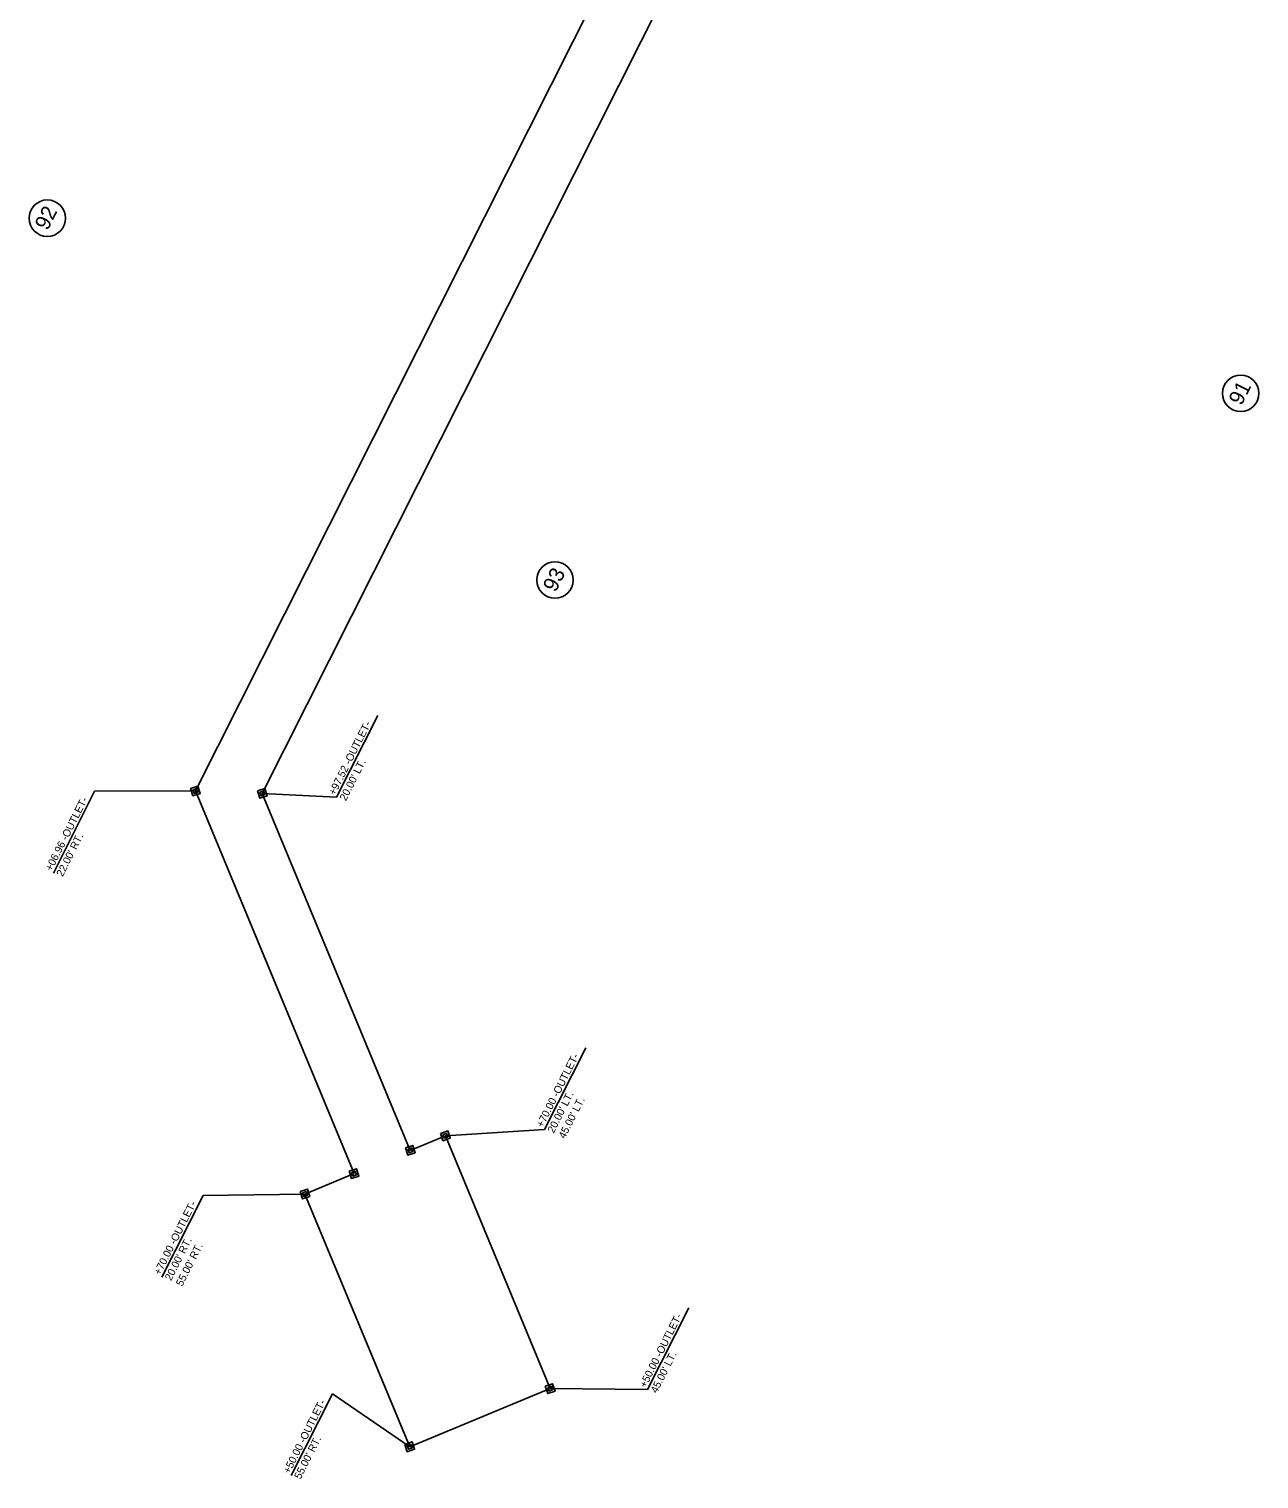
# Model space of a CAD drawing. Extents: x 2010883 to 2014849, y 442000 to 447413.
# Drawn here: x 2010883 to 2011692, y 442000 to 442954 of the extents above; entities that cross this region are included whole.
import ezdxf

# ---------------------------------------------------------------- set-up
doc = ezdxf.new("R2010")
doc.units = 0
for name, color, linetype in [('Prop Easement Permanent Drainage', 7, 'Continuous'), ('Prop Easement Permanent Drainage Station Offsets', 7, 'Continuous'), ('Prop Parcel Number CELL', 7, 'Continuous'), ('Prop Parcel Number Text', 7, 'Continuous'), ('Prop ROW Marker CELL', 7, 'Continuous'), ('Prop ROW Permanent Easement CELL', 7, 'Continuous')]:
    doc.layers.add(name, color=color, linetype=linetype)

msp = doc.modelspace()

# ---------------------------------------------------------------- linework, layer by layer
at = {"layer": 'Prop Easement Permanent Drainage'}
for p, q in [((2010992.44, 442452.82), (2011265.81, 442995.8)), ((2011036.41, 442451.2), (2011301.55, 442977.84)), ((2011096.77, 442201.11), (2010992.44, 442452.82)), ((2011133.72, 442216.42), (2011036.41, 442451.2)), ((2011156.82, 442225.99), (2011133.72, 442216.42)), ((2011225.73, 442059.71), (2011156.82, 442225.99)), ((2011064.44, 442187.71), (2011096.77, 442201.11)), ((2011133.35, 442021.42), (2011064.44, 442187.71)), ((2011133.35, 442021.42), (2011225.73, 442059.71))]:
    msp.add_line(p, q, dxfattribs=at)
at = {"layer": 'Prop Easement Permanent Drainage Station Offsets'}
for p, q in [((2011085.3, 442448.66), (2011112.38, 442502.44)), ((2010899.04, 442398.79), (2010926.12, 442452.58)), ((2010992.44, 442452.82), (2010926.12, 442452.58)), ((2011036.41, 442451.2), (2011085.3, 442448.66)), ((2011221.98, 442230.12), (2011249.06, 442283.9)), ((2011156.82, 442225.99), (2011221.98, 442230.12)), ((2010970.38, 442133.04), (2010997.46, 442186.82)), ((2011064.44, 442187.71), (2010997.46, 442186.82)), ((2011289.76, 442059.07), (2011316.84, 442112.85)), ((2011225.73, 442059.71), (2011289.76, 442059.07)), ((2011055.45, 442002.46), (2011082.53, 442056.24)), ((2011133.35, 442021.42), (2011082.53, 442056.24))]:
    msp.add_line(p, q, dxfattribs=at)
at = {"layer": 'Prop Parcel Number CELL'}
for p, q in [((2010895.01, 442829.52), (2010895.01, 442829.52)), ((2011679.82, 442714.35), (2011679.82, 442714.35)), ((2011228.88, 442591.53), (2011228.88, 442591.53))]:
    msp.add_line(p, q, dxfattribs=at)
for centre in [(2010895.01, 442829.52), (2011679.82, 442714.35), (2011228.88, 442591.53)]:
    msp.add_circle(centre, 12, dxfattribs=at)
at = {"layer": 'Prop ROW Marker CELL'}
for p, q in [((2010992.44, 442452.82), (2010992.44, 442452.82)), ((2011036.41, 442451.2), (2011036.41, 442451.2)), ((2011156.82, 442225.99), (2011156.82, 442225.99)), ((2011133.72, 442216.42), (2011133.72, 442216.42)), ((2011096.77, 442201.11), (2011096.77, 442201.11)), ((2011064.44, 442187.71), (2011064.44, 442187.71)), ((2011225.73, 442059.71), (2011225.73, 442059.71)), ((2011133.35, 442021.42), (2011133.35, 442021.42))]:
    msp.add_line(p, q, dxfattribs=at)
at = {"layer": 'Prop ROW Permanent Easement CELL'}
for points in [[(2010989.23, 442454.44), (2010994.06, 442456.04), (2010995.66, 442451.2), (2010990.82, 442449.6)], [(2010990.84, 442453.63), (2010993.25, 442454.43), (2010994.05, 442452.01), (2010991.63, 442451.21)], [(2011033.2, 442452.82), (2011038.03, 442454.42), (2011039.63, 442449.59), (2011034.79, 442447.99)], [(2011034.81, 442452.01), (2011037.22, 442452.81), (2011038.02, 442450.39), (2011035.6, 442449.6)], [(2011153.6, 442227.61), (2011158.44, 442229.21), (2011160.03, 442224.38), (2011155.2, 442222.78)], [(2011155.21, 442226.8), (2011157.63, 442227.6), (2011158.42, 442225.18), (2011156.01, 442224.39)], [(2011130.51, 442218.04), (2011135.34, 442219.64), (2011136.94, 442214.8), (2011132.1, 442213.21)], [(2011132.11, 442217.23), (2011134.53, 442218.03), (2011135.33, 442215.61), (2011132.91, 442214.81)], [(2011093.55, 442202.73), (2011098.39, 442204.32), (2011099.98, 442199.49), (2011095.15, 442197.89)], [(2011095.16, 442201.92), (2011097.58, 442202.71), (2011098.38, 442200.3), (2011095.96, 442199.5)], [(2011061.22, 442189.32), (2011066.06, 442190.92), (2011067.65, 442186.09), (2011062.82, 442184.49)], [(2011062.83, 442188.52), (2011065.25, 442189.31), (2011066.04, 442186.9), (2011063.63, 442186.1)], [(2011222.52, 442061.33), (2011227.35, 442062.93), (2011228.95, 442058.09), (2011224.12, 442056.49)], [(2011224.13, 442060.52), (2011226.54, 442061.32), (2011227.34, 442058.9), (2011224.93, 442058.1)], [(2011130.14, 442023.04), (2011134.97, 442024.64), (2011136.57, 442019.8), (2011131.74, 442018.21)], [(2011131.75, 442022.23), (2011134.16, 442023.03), (2011134.96, 442020.61), (2011132.55, 442019.81)]]:
    msp.add_lwpolyline(points, close=True, dxfattribs=at)

# ---------------------------------------------------------------- texts
at = {"layer": 'Prop Easement Permanent Drainage Station Offsets'}
for s, p in [('+97.52 -OUTLET-', (2011084.16, 442449.54)), ("20.00' LT.", (2011091.42, 442445.89)), ('+06.96 -OUTLET-', (2010897.9, 442399.68)), ("22.00' RT.", (2010905.16, 442396.02)), ('+70.00 -OUTLET-', (2011220.84, 442231)), ("20.00' LT.", (2011228.1, 442227.35)), ("45.00' LT.", (2011235.36, 442223.69)), ('+70.00 -OUTLET-', (2010969.24, 442133.92)), ("20.00' RT.", (2010976.5, 442130.27)), ("55.00' RT.", (2010983.76, 442126.61)), ('+50.00 -OUTLET-', (2011288.62, 442059.95)), ("45.00' LT.", (2011295.88, 442056.3)), ('+50.00 -OUTLET-', (2011054.31, 442003.34)), ("55.00' RT.", (2011061.57, 441999.69))]:
    msp.add_text(s, height=5, rotation=63.27703, dxfattribs=at).set_placement(p)
at = {"layer": 'Prop Parcel Number Text'}
for s, p in [('92', (2010895.23, 442820.96)), ('91', (2011680.28, 442705.84)), ('93', (2011229.34, 442583.02))]:
    msp.add_text(s, height=10, rotation=63.27703, dxfattribs=at).set_placement(p)

doc.saveas('drawing.dxf')
